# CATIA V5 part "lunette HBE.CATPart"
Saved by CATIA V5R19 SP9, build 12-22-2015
Part number: Part1
Bounding box of the stored display mesh (mm): x -67.998 to 67.998, y -20 to 123.151, z -28.492 to 28.492
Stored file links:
  C:\Users\hbezard\Documents\Perso\imprimante 3d\pieces\lunette transport\lunette HBE.CATPart
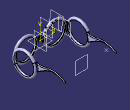
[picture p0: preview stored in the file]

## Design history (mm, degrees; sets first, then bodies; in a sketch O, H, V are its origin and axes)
Set1
  Plane1: type Offset, RefPlane zx-plane, Offset 100
  Plane2: type Offset, RefPlane yz-plane, Offset 60, reversed
  Point1: (-60, 100, 0)
  Line1: type PtDir, RefPoint {point type Coord, X -35, Y 0, Z 0}, Direction (0, 1, 0), Start 0, End 20
  Plane3: type Normal, Curve Sketch8, RefPoint Sketch8.P6
  Plane4: type OffsetPt, RefPlane yz-plane, RefPoint vertex of Line1
Body1 (main body)
  Sketch1 on zx-plane, origin (0, 0, 0), H (0, 0, 1), V (1, 0, 0)
    point P1 (-13, 0)
    line L1 (-13, 0) -> (-13, -9)
    line L2 (-13, -9) -> (1.4, -4.8)
    arc A1 centre (0, 0) radius 5 from (1.4, -4.8) to (5, 0) ccw
    point P4 (0, 0)
    point P5 (5, 0)
    line L3 (5, 0) -> (-13, 0)
    reference intersected line E1 through (0, 0) direction (0, 1) from xy-plane
    length L2 = 15
    length L1 = 9
    radius A1 = 5
    coincidence: P1 H, P5 H, P4 L3, P4 E1
    vertical: L1 V
    tangency: A1 L2
    horizontal: L3 H
  Pad1: profile Sketch1, direction (0, 1, 0), length 5, mirrored extent
  Sketch2 on Plane2, origin (-60, 0, 0), H (0, 1, 0), V (0, 0, 1)
    circle A1 centre (100, 0) radius 10
    reference projected point E1 (100, 0) from Point1
    radius A1 = 10
    concentricity: A1 E1
  Pad2: profile Sketch2, direction (1, 0, 0), length 5, mirrored extent
  Sketch3 on xy-plane, origin (0, 0, 0), H (1, 0, 0), V (0, 1, 0)
    arc A1 centre (-9.5, 0) radius 3 from (-6.5, 0) to (-11, 2.5981) ccw
    point P1 (-9.5, 0)
    arc A2 centre (-12.5, 0) radius 3 from (-9.5, 0) to (-11, 2.5981) ccw
    point P2 (-12.5, 0)
    reference intersected line E1 through (0, 0) direction (-1, 0) from zx-plane
    reference intersected line E2 through (0, 0) direction (-1, 0) from zx-plane
    axis line L1 (-35, 5.0345) -> (-35, -8.3344)
    arc A3 centre (-9.5, 0) radius 3 from (-11, -2.5981) to (-6.5, 0) ccw
    point P5 (-6.5, 0)
    point P6 (-6.5, 0)
    arc A4 centre (-12.5, 0) radius 3 from (-11, -2.5981) to (-9.5, 0) ccw
    point P7 (-9.5, 0)
    point P8 (-9.5, 0)
    reference projected line E3 (-35, -20) -> (-35, 0) from Line1
    distance P2 P1 = 3
    radius A2 = 3
    radius A1 = 3
    distance L1 P2 = 22.5
    coincidence: P2 E1, P1 E2, A1 A3, A2 A4, L1 E3, P5 P6, P7 P8
    vertical: L1 V
Body2
  Sketch4 on xy-plane, origin (0, 0, 0), H (1, 0, 0), V (0, 1, 0)
    arc A1 centre (-9.5, 0) radius 3 from (-6.5, 0) to (-11, 2.5981) ccw
    point P1 (-9.5, 0)
    arc A2 centre (-12.5, 0) radius 3 from (-9.5, 0) to (-11, 2.5981) ccw
    point P2 (-12.5, 0)
    reference intersected line E1 through (0, 0) direction (-1, 0) from zx-plane
    reference intersected line E2 through (0, 0) direction (-1, 0) from zx-plane
    axis line L1 (-35, 5.0345) -> (-35, -8.3344)
    arc A3 centre (-9.5, 0) radius 3 from (-11, -2.5981) to (-6.5, 0) ccw
    point P5 (-6.5, 0)
    point P6 (-6.5, 0)
    arc A4 centre (-12.5, 0) radius 3 from (-11, -2.5981) to (-9.5, 0) ccw
    point P7 (-9.5, 0)
    point P8 (-9.5, 0)
    reference projected line E3 (-35, -20) -> (-35, 0) from Line1
    distance P2 P1 = 3
    radius A2 = 3
    radius A1 = 3
    distance L1 P2 = 22.5
    coincidence: P2 E1, P1 E2, A1 A3, A2 A4, L1 E3, P5 P6, P7 P8
    vertical: L1 V
  Shaft1: profile Sketch4, axis Sketch4.L1, angle 360
  Sketch5 on xy-plane, origin (0, 0, 0), H (1, 0, 0), V (0, 1, 0)
    arc A1 centre (-65, 3) radius 3 from (-62.0114, 2.7389) to (-62.4019, 4.5) ccw
    point P1 (-65, 3)
    point P2 (-65, 6)
    construction line L1 (-65, 28.8094) -> (-65, 9.3354)
    arc A2 centre (-65, 3) radius 3 from (-67.5981, 4.5) to (-62.0114, 2.7389) ccw
    point P5 (-62.0114, 2.7389)
    point P6 (-62.0114, 2.7389)
    arc A3 centre (-65, 6) radius 3 from (-67.5981, 4.5) to (-62.4019, 4.5) ccw
    axis line L2 (-77.6916, 28.5) -> (-47.473, 28.5)
    reference intersected line E1 through (0, 0) direction (-1, 0) from zx-plane
    reference intersected line E2 through (-60, 0) direction (0, 1) from Plane2
    distance P2 P1 = 3
    radius A1 = 3
    distance A2 E1 = 0
    radius A3 = 3
    distance P2 L2 = 22.5
    distance E2 L1 = 5
    perpendicularity: L2 L1
    coincidence: P6 P5, P2 L1, P1 L1
  Shaft2: profile Sketch5, axis Sketch5.L2, angle 360
  Sketch6 on zx-plane, origin (0, 0, 0), H (0, 0, 1), V (1, 0, 0)
    spline S1 through (4.1715, -8.1459) (9.4122, -4.3898) (11.2076, 0)
    spline S2 through (-9.9293, -8.9423) (-1.2054, -5.9306) (5.1855, -2.8953) (6.3824, 0)
    projected circle E1 centre (0, -35) radius 28.5 from edge [face of Shaft1 from Sketch4.A1 | face of Shaft1 from Sketch4.A3]
    line L1 (6.3824, 0) -> (11.2076, 0)
    point P1 (6.3824, 0)
    point P2 (11.2076, 0)
    offset circle E3 centre (0, -35) radius 28 from edge [face of Shaft1 from Sketch4.A1 | face of Shaft1 from Sketch4.A3]
    offset arc E4 centre (0, -35) radius 28 from (5.5614, -7.5579) to (-9.3263, -8.5989) ccw from edge [face of Shaft1 from Sketch4.A1 | face of Shaft1 from Sketch4.A3]
    point P5 (11.2076, 0)
    point P6 (6.3824, 0)
    coincidence: P5 H, P6 H, P6 P1, P5 P2
    horizontal: L1 H
  Pad3: profile Sketch6, direction (0, 1, 0), length 2
  Fillet1: radius 9, on edge [start face of Pad3 | face of Shaft1 from Sketch4.A3]
  Fillet2: radius 0.11, on edge [face of Pad3 from Sketch6.E4 | end face of Pad3]
  Fillet3: radius 0.11, on edge [face of Pad3 from Sketch6.E4 | face of Shaft1 from Sketch4.A1]
  Fillet4: radius 1.11, on edge [face of Pad3 from Sketch6.S2 | end face of Pad3]
  Fillet5: radius 0.5, on edge [start face of Pad3 | face of Pad3 from Sketch6.S2]
  Fillet6: radius 0.5, on edge [face of Pad3 from Sketch6.S1 | end face of Pad3]; edge [start face of Pad3 | face of Pad3 from Sketch6.S1]
  Fillet7: radius 0.5, on edge [face of Pad3 from Sketch6.S1 | face of Shaft1]
  Fillet8: radius 1.5, on edge [face of Shaft1 | face of Shaft2 from Sketch5.A2]
  Sketch7 on Plane2, origin (-60, 0, 0), H (0, 1, 0), V (0, 0, 1)
    projected arc E1 centre (28.5, 0) radius 25.7611 from (4.3445, -8.9523) to (4.3445, 8.9523) ccw from edge [face of Shaft2 from Sketch5.A2 | face of Shaft2 from Sketch5.A1]
    projected arc E2 centre (28.5, 0) radius 25.7611 from (53.122, -7.5755) to (49.9464, 14.2718) ccw from edge [face of Shaft2 from Sketch5.A2 | face of Shaft2 from Sketch5.A1]
    spline S1 through (120.7164, 3.9449) (107.5754, 9.7962) (99.1692, 11.522) (81.7803, 8.4657) (71.4697, 3.3588) (57.2526, -5.1849) (50.7179, -8.9184)
    spline S2 through (122.3171, 6.7756) (113.4231, 11.1212) (98.9336, 15.2605) (56.852, 12.0692) (48.814, 14.811)
    arc A1 centre (121.5271, 5.3544) radius 1.626 from (120.7164, 3.9449) to (122.3171, 6.7756) ccw
    point P3 (120.7164, 3.9449)
    point P4 (122.3171, 6.7756)
    point P8 (120.7164, 3.9449)
    point P9 (122.3171, 6.7756)
    coincidence: P8 P3, P9 P4
    tangency: A1 S1, A1 S2
  Pad4: profile Sketch7, direction (-1, 0, 0), length 3
  Fillet9: radius 2, on edge [face of Pad4 from Sketch7.E2 | face of Shaft2 from Sketch5.A1]
  Fillet10: radius 1.5, on edge [face of Pad4 from Sketch7.E2 | start face of Pad4]
  Fillet11: radius 1.5, on edge [face of Pad4 from Sketch7.S2 | start face of Pad4]
  Fillet12: radius 1.5, on end face of Pad4
  Mirror1: of the body so far, about yz-plane
Body3
  Sketch8 on zx-plane, origin (0, 0, 0), H (-1, 0, 0), V (0, 0, 1)
    arc A1 centre (35, 0) radius 22.5 from (38.9071, 22.1582) to (31.0929, 22.1582) ccw
    point P1 (35, 0)
    reference projected point E1 (35, 0) from vertex of Line1
    reference projected circle E2 centre (35, 0) radius 25.5 from edge [face of Shaft1 from Sketch4.A4 | face of Shaft1 from Sketch4.A2]
    axis line L1 (35, 7.5958) -> (35, -7.5958)
    construction line L2 (35, 0) -> (31.0929, 22.1582)
    point P4 (35, 0)
    construction line L3 (35, 0) -> (38.9071, 22.1582)
    point P6 (38.9071, 22.1582)
    distance A1 E2 = 3
    angle L2 L1 = 10
    coincidence: P1 E1
    vertical: L1 V
    midpoint: L1 P1
    symmetry: P1 P4 L1, L2 L3 L1
  Sketch9 on Plane4, origin (-35, -20, 0), H (0, 1, 0), V (0, 0, 1)
    circle A1 centre (20, 22.5) radius 0.5
    point P1 (20, 22.5)
    circle A2 centre (20, 22.5) radius 1.5
    point P2 (20, 22.5)
    radius A1 = 0.5
    radius A2 = 1.5
    radius A2 = 1.5 (reference)
    coincidence: P1 P2
  Shaft3: profile Sketch9, axis Line1, angle 10, second angle 10
  Chamfer1: length 1, angle 30, on edge [face of Shaft3 | face of Shaft3 from Sketch9.A2]
  Chamfer2: length 1, angle 30, on edge [face of Shaft3 from Sketch9.A2 | face of Shaft3]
